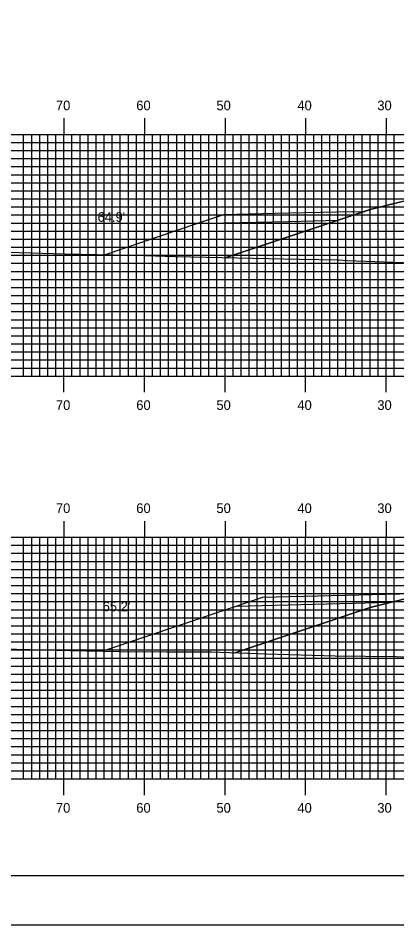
# Model space of a CAD drawing. Extents: x 1807832 to 1808175, y 442591 to 442811.
# Drawn here: x 1807922.1 to 1807969.1, y 442590.5 to 442703.1 of the extents above; entities that cross this region are included whole.
import ezdxf

# ---------------------------------------------------------------- set-up
doc = ezdxf.new("R2010")
doc.units = 0
for name, color, linetype in [('BORDER', 7, 'Continuous'), ('D_Roadway_Centerline', 7, 'Continuous'), ('D_Roadway_Drive_Gravel', 7, 'Continuous'), ('D_Roadway_SlopeLines', 7, 'Continuous'), ('D_Text_Standard', 7, 'Continuous'), ('H_V ANNOTATION', 7, 'Continuous'), ('MAJOR', 7, 'Continuous'), ('MINOR', 7, 'Continuous'), ('PLOT BOUNDARY', 7, 'Continuous'), ('S_Roadway_Centerline', 7, 'Continuous')]:
    doc.layers.add(name, color=color, linetype=linetype)

msp = doc.modelspace()

# ---------------------------------------------------------------- linework, layer by layer
at = {"layer": 'BORDER'}
msp.add_lwpolyline([(1807848.18, 442596.67), (1808168.18, 442596.67), (1808168.18, 442806.67), (1807848.18, 442806.67)], close=True, dxfattribs=at)
at = {"layer": 'D_Roadway_Centerline'}
for points in [[(1807947.93, 442673.38), (1807965.78, 442679.34), (1807969.42, 442680.25), (1807977.78, 442682.34), (1807985.78, 442682.66), (1807997.78, 442682.9), (1808009.78, 442682.66), (1808017.78, 442682.34), (1808026.15, 442680.25), (1808029.78, 442679.34), (1808056.5, 442670.43)], [(1807948.98, 442624.33), (1807965.78, 442629.93), (1807969.42, 442630.84), (1807977.78, 442632.93), (1807985.78, 442633.25), (1807997.78, 442633.49), (1808009.78, 442633.25), (1808017.78, 442632.93), (1808026.15, 442630.84), (1808029.78, 442629.93), (1808055.58, 442621.33)]]:
    msp.add_lwpolyline(points, dxfattribs=at)
at = {"layer": 'D_Roadway_Drive_Gravel'}
msp.add_lwpolyline([(1807963.65, 442679.08), (1807955.61, 442678.88), (1807947.57, 442678.68), (1807944.37, 442677.6), (1807947.57, 442677.68), (1807955.61, 442677.88), (1807961.88, 442678.04)], dxfattribs=at)
at = {"layer": 'D_Roadway_SlopeLines'}
for p, q in [((1807963.65, 442679.08), (1807965.12, 442679.12)), ((1807949.21, 442630.11), (1807968.41, 442630.59))]:
    msp.add_line(p, q, dxfattribs=at)
for points in [[(1807977.78, 442682.34), (1807965.78, 442679.34), (1807947.93, 442673.38)], [(1807947.57, 442678.68), (1807944.37, 442677.6), (1807932.89, 442673.74)], [(1807977.78, 442632.93), (1807965.78, 442629.93), (1807948.98, 442624.33)], [(1807972.85, 442631.7), (1807952.42, 442631.19), (1807932.59, 442624.52)]]:
    msp.add_lwpolyline(points, dxfattribs=at)
at = {"layer": 'MAJOR'}
for p, q in [((1807927.78, 442690.67), (1807927.78, 442688.67)), ((1807937.78, 442690.67), (1807937.78, 442688.67)), ((1807947.78, 442690.67), (1807947.78, 442688.67)), ((1807957.78, 442690.67), (1807957.78, 442688.67)), ((1807967.78, 442690.67), (1807967.78, 442688.67)), ((1807857.78, 442688.67), (1808137.78, 442688.67)), ((1807857.78, 442688.67), (1808137.78, 442688.67)), ((1807927.78, 442658.67), (1807927.78, 442688.67)), ((1807937.78, 442658.67), (1807937.78, 442688.67)), ((1807947.78, 442658.67), (1807947.78, 442688.67)), ((1807957.78, 442658.67), (1807957.78, 442688.67)), ((1807967.78, 442658.67), (1807967.78, 442688.67)), ((1807857.78, 442683.67), (1808137.78, 442683.67)), ((1807857.78, 442678.67), (1808137.78, 442678.67)), ((1807857.78, 442673.67), (1808137.78, 442673.67)), ((1807857.78, 442668.67), (1808137.78, 442668.67)), ((1807857.78, 442663.67), (1808137.78, 442663.67)), ((1807857.78, 442658.67), (1808137.78, 442658.67)), ((1807857.78, 442658.67), (1808137.78, 442658.67)), ((1807927.78, 442656.66), (1807927.78, 442658.67)), ((1807937.78, 442656.66), (1807937.78, 442658.67)), ((1807947.78, 442656.66), (1807947.78, 442658.67)), ((1807957.78, 442656.66), (1807957.78, 442658.67)), ((1807967.78, 442656.66), (1807967.78, 442658.67)), ((1807927.78, 442640.67), (1807927.78, 442638.67)), ((1807937.78, 442640.67), (1807937.78, 442638.67)), ((1807947.78, 442640.67), (1807947.78, 442638.67)), ((1807957.78, 442640.67), (1807957.78, 442638.67)), ((1807967.78, 442640.67), (1807967.78, 442638.67)), ((1807857.78, 442638.67), (1808137.78, 442638.67)), ((1807857.78, 442638.67), (1808137.78, 442638.67)), ((1807927.78, 442608.67), (1807927.78, 442638.67)), ((1807937.78, 442608.67), (1807937.78, 442638.67)), ((1807947.78, 442608.67), (1807947.78, 442638.67)), ((1807957.78, 442608.67), (1807957.78, 442638.67)), ((1807967.78, 442608.67), (1807967.78, 442638.67)), ((1807857.78, 442633.67), (1808137.78, 442633.67)), ((1807857.78, 442628.67), (1808137.78, 442628.67)), ((1807857.78, 442623.67), (1808137.78, 442623.67)), ((1807857.78, 442618.67), (1808137.78, 442618.67)), ((1807857.78, 442613.67), (1808137.78, 442613.67)), ((1807857.78, 442608.67), (1808137.78, 442608.67)), ((1807857.78, 442608.67), (1808137.78, 442608.67)), ((1807927.78, 442606.66), (1807927.78, 442608.67)), ((1807937.78, 442606.66), (1807937.78, 442608.67)), ((1807947.78, 442606.66), (1807947.78, 442608.67)), ((1807957.78, 442606.66), (1807957.78, 442608.67)), ((1807967.78, 442606.66), (1807967.78, 442608.67))]:
    msp.add_line(p, q, dxfattribs=at)
at = {"layer": 'MINOR'}
for p, q in [((1807922.78, 442658.67), (1807922.78, 442688.67)), ((1807923.78, 442658.67), (1807923.78, 442688.67)), ((1807924.78, 442658.67), (1807924.78, 442688.67)), ((1807925.78, 442658.67), (1807925.78, 442688.67)), ((1807926.78, 442658.67), (1807926.78, 442688.67)), ((1807928.78, 442658.67), (1807928.78, 442688.67)), ((1807929.78, 442658.67), (1807929.78, 442688.67)), ((1807930.78, 442658.67), (1807930.78, 442688.67)), ((1807931.78, 442658.67), (1807931.78, 442688.67)), ((1807932.78, 442658.67), (1807932.78, 442688.67)), ((1807933.78, 442658.67), (1807933.78, 442688.67)), ((1807934.78, 442658.67), (1807934.78, 442688.67)), ((1807935.78, 442658.67), (1807935.78, 442688.67)), ((1807936.78, 442658.67), (1807936.78, 442688.67)), ((1807938.78, 442658.67), (1807938.78, 442688.67)), ((1807939.78, 442658.67), (1807939.78, 442688.67)), ((1807940.78, 442658.67), (1807940.78, 442688.67)), ((1807941.78, 442658.67), (1807941.78, 442688.67)), ((1807942.78, 442658.67), (1807942.78, 442688.67)), ((1807943.78, 442658.67), (1807943.78, 442688.67)), ((1807944.78, 442658.67), (1807944.78, 442688.67)), ((1807945.78, 442658.67), (1807945.78, 442688.67)), ((1807946.78, 442658.67), (1807946.78, 442688.67)), ((1807948.78, 442658.67), (1807948.78, 442688.67)), ((1807949.78, 442658.67), (1807949.78, 442688.67)), ((1807950.78, 442658.67), (1807950.78, 442688.67)), ((1807951.78, 442658.67), (1807951.78, 442688.67)), ((1807952.78, 442658.67), (1807952.78, 442688.67)), ((1807953.78, 442658.67), (1807953.78, 442688.67)), ((1807954.78, 442658.67), (1807954.78, 442688.67)), ((1807955.78, 442658.67), (1807955.78, 442688.67)), ((1807956.78, 442658.67), (1807956.78, 442688.67)), ((1807958.78, 442658.67), (1807958.78, 442688.67)), ((1807959.78, 442658.67), (1807959.78, 442688.67)), ((1807960.78, 442658.67), (1807960.78, 442688.67)), ((1807961.78, 442658.67), (1807961.78, 442688.67)), ((1807962.78, 442658.67), (1807962.78, 442688.67)), ((1807963.78, 442658.67), (1807963.78, 442688.67)), ((1807964.78, 442658.67), (1807964.78, 442688.67)), ((1807965.78, 442658.67), (1807965.78, 442688.67)), ((1807966.78, 442658.67), (1807966.78, 442688.67)), ((1807968.78, 442658.67), (1807968.78, 442688.67)), ((1807857.78, 442687.67), (1808137.78, 442687.67)), ((1807857.78, 442686.67), (1808137.78, 442686.67)), ((1807857.78, 442685.67), (1808137.78, 442685.67)), ((1807857.78, 442684.67), (1808137.78, 442684.67)), ((1807857.78, 442682.67), (1808137.78, 442682.67)), ((1807857.78, 442681.67), (1808137.78, 442681.67)), ((1807857.78, 442680.67), (1808137.78, 442680.67)), ((1807857.78, 442679.67), (1808137.78, 442679.67)), ((1807857.78, 442677.67), (1808137.78, 442677.67)), ((1807857.78, 442676.67), (1808137.78, 442676.67)), ((1807857.78, 442675.67), (1808137.78, 442675.67)), ((1807857.78, 442674.67), (1808137.78, 442674.67)), ((1807857.78, 442672.67), (1808137.78, 442672.67)), ((1807857.78, 442671.67), (1808137.78, 442671.67)), ((1807857.78, 442670.67), (1808137.78, 442670.67)), ((1807857.78, 442669.67), (1808137.78, 442669.67)), ((1807857.78, 442667.67), (1808137.78, 442667.67)), ((1807857.78, 442666.67), (1808137.78, 442666.67)), ((1807857.78, 442665.67), (1808137.78, 442665.67)), ((1807857.78, 442664.67), (1808137.78, 442664.67)), ((1807857.78, 442662.67), (1808137.78, 442662.67)), ((1807857.78, 442661.67), (1808137.78, 442661.67)), ((1807857.78, 442660.67), (1808137.78, 442660.67)), ((1807857.78, 442659.67), (1808137.78, 442659.67)), ((1807922.78, 442608.67), (1807922.78, 442638.67)), ((1807923.78, 442608.67), (1807923.78, 442638.67)), ((1807924.78, 442608.67), (1807924.78, 442638.67)), ((1807925.78, 442608.67), (1807925.78, 442638.67)), ((1807926.78, 442608.67), (1807926.78, 442638.67)), ((1807928.78, 442608.67), (1807928.78, 442638.67)), ((1807929.78, 442608.67), (1807929.78, 442638.67)), ((1807930.78, 442608.67), (1807930.78, 442638.67)), ((1807931.78, 442608.67), (1807931.78, 442638.67)), ((1807932.78, 442608.67), (1807932.78, 442638.67)), ((1807933.78, 442608.67), (1807933.78, 442638.67)), ((1807934.78, 442608.67), (1807934.78, 442638.67)), ((1807935.78, 442608.67), (1807935.78, 442638.67)), ((1807936.78, 442608.67), (1807936.78, 442638.67)), ((1807938.78, 442608.67), (1807938.78, 442638.67)), ((1807939.78, 442608.67), (1807939.78, 442638.67)), ((1807940.78, 442608.67), (1807940.78, 442638.67)), ((1807941.78, 442608.67), (1807941.78, 442638.67)), ((1807942.78, 442608.67), (1807942.78, 442638.67)), ((1807943.78, 442608.67), (1807943.78, 442638.67)), ((1807944.78, 442608.67), (1807944.78, 442638.67)), ((1807945.78, 442608.67), (1807945.78, 442638.67)), ((1807946.78, 442608.67), (1807946.78, 442638.67)), ((1807948.78, 442608.67), (1807948.78, 442638.67)), ((1807949.78, 442608.67), (1807949.78, 442638.67)), ((1807950.78, 442608.67), (1807950.78, 442638.67)), ((1807951.78, 442608.67), (1807951.78, 442638.67)), ((1807952.78, 442608.67), (1807952.78, 442638.67)), ((1807953.78, 442608.67), (1807953.78, 442638.67)), ((1807954.78, 442608.67), (1807954.78, 442638.67)), ((1807955.78, 442608.67), (1807955.78, 442638.67)), ((1807956.78, 442608.67), (1807956.78, 442638.67)), ((1807958.78, 442608.67), (1807958.78, 442638.67)), ((1807959.78, 442608.67), (1807959.78, 442638.67)), ((1807960.78, 442608.67), (1807960.78, 442638.67)), ((1807961.78, 442608.67), (1807961.78, 442638.67)), ((1807962.78, 442608.67), (1807962.78, 442638.67)), ((1807963.78, 442608.67), (1807963.78, 442638.67)), ((1807964.78, 442608.67), (1807964.78, 442638.67)), ((1807965.78, 442608.67), (1807965.78, 442638.67)), ((1807966.78, 442608.67), (1807966.78, 442638.67)), ((1807968.78, 442608.67), (1807968.78, 442638.67)), ((1807857.78, 442637.67), (1808137.78, 442637.67)), ((1807857.78, 442636.67), (1808137.78, 442636.67)), ((1807857.78, 442635.67), (1808137.78, 442635.67)), ((1807857.78, 442634.67), (1808137.78, 442634.67)), ((1807857.78, 442632.67), (1808137.78, 442632.67)), ((1807857.78, 442631.67), (1808137.78, 442631.67)), ((1807857.78, 442630.67), (1808137.78, 442630.67)), ((1807857.78, 442629.67), (1808137.78, 442629.67)), ((1807857.78, 442627.67), (1808137.78, 442627.67)), ((1807857.78, 442626.67), (1808137.78, 442626.67)), ((1807857.78, 442625.67), (1808137.78, 442625.67)), ((1807857.78, 442624.67), (1808137.78, 442624.67)), ((1807857.78, 442622.67), (1808137.78, 442622.67)), ((1807857.78, 442621.67), (1808137.78, 442621.67)), ((1807857.78, 442620.67), (1808137.78, 442620.67)), ((1807857.78, 442619.67), (1808137.78, 442619.67)), ((1807857.78, 442617.67), (1808137.78, 442617.67)), ((1807857.78, 442616.67), (1808137.78, 442616.67)), ((1807857.78, 442615.67), (1808137.78, 442615.67)), ((1807857.78, 442614.67), (1808137.78, 442614.67)), ((1807857.78, 442612.67), (1808137.78, 442612.67)), ((1807857.78, 442611.67), (1808137.78, 442611.67)), ((1807857.78, 442610.67), (1808137.78, 442610.67)), ((1807857.78, 442609.67), (1808137.78, 442609.67))]:
    msp.add_line(p, q, dxfattribs=at)
at = {"layer": 'PLOT BOUNDARY'}
msp.add_lwpolyline([(1807832, 442590.55), (1808172, 442590.55), (1808172, 442810.55), (1807832, 442810.55)], close=True, dxfattribs=at)
at = {"layer": 'S_Roadway_Centerline'}
for points in [[(1807920.78, 442674.04), (1807927.94, 442673.83), (1807937.9, 442673.65), (1807941.59, 442673.52), (1807957.03, 442673.2), (1807961.87, 442673.09), (1807962.44, 442673.08), (1807962.93, 442673.04), (1807974.42, 442672.61), (1807985.09, 442672.31), (1807986.24, 442672.3), (1808005.67, 442672.1), (1808013.86, 442671.86), (1808020.57, 442671.59), (1808025.47, 442671.48), (1808031.6, 442671.2), (1808040.68, 442670.56), (1808045.09, 442670.26), (1808048.48, 442670.29), (1808055.42, 442670.49), (1808065.01, 442670.01)], [(1807918.52, 442624.84), (1807928.55, 442624.62), (1807934.62, 442624.47), (1807940.55, 442624.44), (1807946.05, 442624.44), (1807952.88, 442624.18), (1807961.44, 442623.96), (1807969.02, 442623.87), (1807978.89, 442623.42), (1807981.16, 442623.31), (1807983.05, 442623.35), (1807999.11, 442623.46), (1808003.69, 442623.48), (1808004.14, 442623.48), (1808004.76, 442623.45), (1808025.99, 442622.22), (1808027.17, 442622.16), (1808029.09, 442622.08), (1808039.32, 442621.67), (1808046.99, 442621.44), (1808051.51, 442621.31), (1808056.36, 442621.34), (1808068.31, 442621.1)]]:
    msp.add_lwpolyline(points, dxfattribs=at)

# ---------------------------------------------------------------- texts
at = {"layer": 'D_Text_Standard'}
for s, p in [("64.9'", (1807931.95, 442677.82)), ("65.2'", (1807932.59, 442629.48))]:
    msp.add_text(s, height=1.2, dxfattribs=at).set_placement(p)
at = {"layer": 'H_V ANNOTATION'}
for s, p in [('70', (1807926.79, 442691.67)), ('60', (1807936.76, 442691.67)), ('50', (1807946.71, 442691.67)), ('40', (1807956.76, 442691.67)), ('30', (1807966.68, 442691.67)), ('70', (1807926.79, 442654.47)), ('60', (1807936.76, 442654.47)), ('50', (1807946.71, 442654.47)), ('40', (1807956.76, 442654.47)), ('30', (1807966.68, 442654.47)), ('70', (1807926.79, 442641.67)), ('60', (1807936.76, 442641.67)), ('50', (1807946.71, 442641.67)), ('40', (1807956.76, 442641.67)), ('30', (1807966.68, 442641.67)), ('70', (1807926.79, 442604.47)), ('60', (1807936.76, 442604.47)), ('50', (1807946.71, 442604.47)), ('40', (1807956.76, 442604.47)), ('30', (1807966.68, 442604.47))]:
    msp.add_text(s, height=1.2, dxfattribs=at).set_placement(p)

doc.saveas('drawing.dxf')
